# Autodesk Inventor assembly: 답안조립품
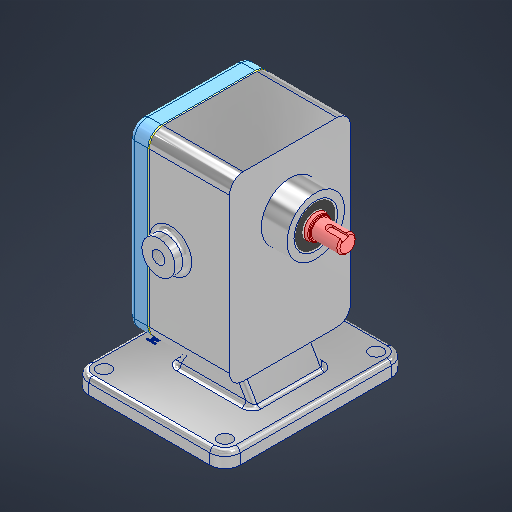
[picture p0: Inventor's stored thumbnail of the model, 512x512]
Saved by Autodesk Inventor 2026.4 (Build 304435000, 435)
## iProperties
Created: 2026-10
Part Number: 답안조립품
Document SubType Name: Assembly
Designer: user
Author: user
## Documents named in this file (11)
- C:\Users\user\Desktop\761003V1009\답안조립품.iam
- C:\Users\user\Desktop\761003V1009\본체.ipt
- C:\Users\user\Desktop\761003V1009\베어링 부시\베어링 부시.ipt
- C:\Users\user\Desktop\761003V1009\구동 축\구동 축.ipt
- C:\Users\user\Desktop\761003V1009\종동 축\종동 축.ipt
- C:\Users\user\Desktop\761003V1009\평행 키 6x6x18\평행 키 6x6x18.ipt
- C:\Users\user\Desktop\761003V1009\스퍼 기어\스퍼 기어.ipt
- C:\Users\user\Desktop\761003V1009\개스킷\개스킷.ipt
- C:\Users\user\Desktop\761003V1009\커버\커버.ipt
- C:\Users\user\Desktop\761003V1009\6각 구멍붙이 볼트 M5x16\6각 구멍붙이 볼트 M5x16.ipt
- C:\Users\user\Desktop\761003V1009\오일 실 16 28 7\오일 실 16 28 7.ipt
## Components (10 placed, 3 different names)
1. 구동 축:1
2. 개스킷:1
3. 6각 구멍붙이 볼트 M5x16:1
4. 6각 구멍붙이 볼트 M5x16:2
5. 6각 구멍붙이 볼트 M5x16:3
6. 6각 구멍붙이 볼트 M5x16:4
7. 6각 구멍붙이 볼트 M5x16:5
8. 6각 구멍붙이 볼트 M5x16:6
9. 6각 구멍붙이 볼트 M5x16:7
10. 6각 구멍붙이 볼트 M5x16:8
